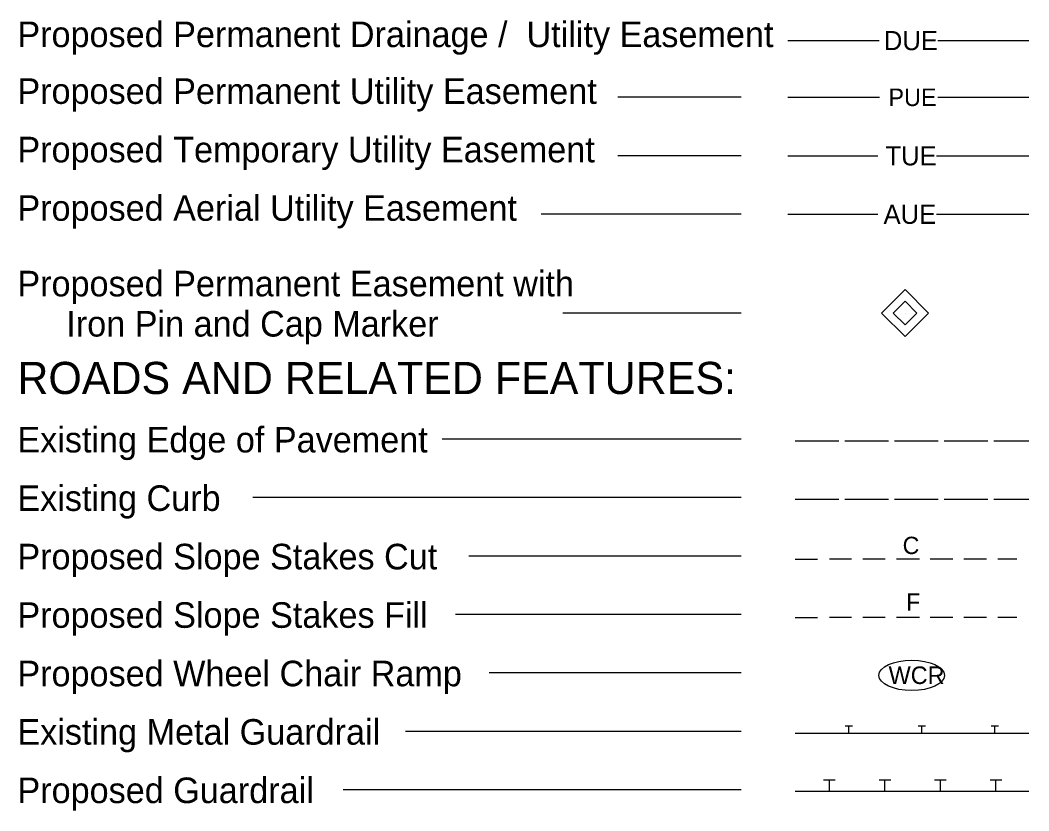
# Model space of a CAD drawing. Extents: x 573855 to 575539, y -53293 to -50956.
# Drawn here: x 574418.1 to 574763.4, y -53027.3 to -52756.7 of the extents above; entities that cross this region are included whole.
import ezdxf

# ---------------------------------------------------------------- set-up
doc = ezdxf.new("R2010")
doc.units = 0
for name, color, linetype in [('Prop Easement Permanent Drainage Utility', 7, 'Continuous'), ('Prop ROW Permanent Easement CELL', 7, 'Continuous'), ('Sheet Symbology CELL', 7, 'Continuous')]:
    doc.layers.add(name, color=color, linetype=linetype)

msp = doc.modelspace()

# ---------------------------------------------------------------- linework, layer by layer
at = {"layer": 'Prop Easement Permanent Drainage Utility'}
for p, q in [((574680.91, -52763.7), (574712.21, -52763.7)), ((574732.21, -52763.7), (574763.41, -52763.7))]:
    msp.add_line(p, q, dxfattribs=at)
at = {"layer": 'Prop ROW Permanent Easement CELL'}
msp.add_line((574721.05, -52856.95), (574721.05, -52856.95), dxfattribs=at)
for points in [[(574721.05, -52848.9), (574729.1, -52856.95), (574721.05, -52865), (574713, -52856.95)], [(574721.05, -52852.92), (574725.08, -52856.95), (574721.05, -52860.98), (574717.02, -52856.95)]]:
    msp.add_lwpolyline(points, close=True, dxfattribs=at)
at = {"layer": 'Sheet Symbology CELL'}
for p, q in [((574664.88, -52783.13), (574622.74, -52783.13)), ((574680.91, -52783.13), (574684.74, -52783.13)), ((574684.74, -52783.13), (574712.24, -52783.13)), ((574732.24, -52783.13), (574759.74, -52783.13)), ((574759.74, -52783.13), (574763.41, -52783.13)), ((574664.88, -52803.13), (574622.74, -52803.13)), ((574680.91, -52803.13), (574684.26, -52803.13)), ((574684.26, -52803.13), (574711.76, -52803.13)), ((574731.76, -52803.13), (574759.26, -52803.13)), ((574759.26, -52803.13), (574763.41, -52803.13)), ((574664.88, -52823.13), (574596.42, -52823.13)), ((574680.91, -52823.13), (574684.26, -52823.13)), ((574684.26, -52823.13), (574711.76, -52823.13)), ((574731.76, -52823.13), (574759.26, -52823.13)), ((574759.26, -52823.13), (574763.41, -52823.13)), ((574664.88, -52856.95), (574603.87, -52856.95)), ((574664.88, -52900.11), (574562.53, -52900.11)), ((574683.41, -52900.68), (574698.41, -52900.68)), ((574700.41, -52900.68), (574715.41, -52900.68)), ((574717.41, -52900.68), (574732.41, -52900.68)), ((574734.41, -52900.68), (574749.41, -52900.68)), ((574751.41, -52900.68), (574763.41, -52900.68)), ((574664.88, -52920.11), (574497.73, -52920.11)), ((574683.41, -52920.68), (574698.41, -52920.68)), ((574700.41, -52920.68), (574715.41, -52920.68)), ((574717.41, -52920.68), (574732.41, -52920.68)), ((574734.41, -52920.68), (574749.41, -52920.68)), ((574751.41, -52920.68), (574763.41, -52920.68)), ((574664.88, -52940.11), (574571.69, -52940.11)), ((574683.41, -52941.16), (574691.01, -52941.16)), ((574702.71, -52941.16), (574695.16, -52941.16)), ((574714.21, -52941.16), (574706.61, -52941.16)), ((574725.96, -52941.16), (574718.16, -52941.16)), ((574737.41, -52941.16), (574729.66, -52941.16)), ((574748.96, -52941.16), (574741.11, -52941.16)), ((574759.26, -52941.16), (574752.86, -52941.16)), ((574664.88, -52960.11), (574567.14, -52960.11)), ((574683.41, -52961.16), (574691.01, -52961.16)), ((574702.71, -52961.16), (574695.16, -52961.16)), ((574714.21, -52961.16), (574706.61, -52961.16)), ((574725.96, -52961.16), (574718.16, -52961.16)), ((574737.41, -52961.16), (574729.66, -52961.16)), ((574748.96, -52961.16), (574741.11, -52961.16)), ((574759.26, -52961.16), (574752.86, -52961.16)), ((574664.88, -52980.11), (574578.61, -52980.11)), ((574700.56, -52998.17), (574703.06, -52998.17)), ((574701.81, -53000.67), (574701.81, -52998.17)), ((574725.56, -52998.17), (574728.06, -52998.17)), ((574726.81, -53000.67), (574726.81, -52998.17)), ((574750.56, -52998.17), (574753.06, -52998.17)), ((574751.81, -53000.67), (574751.81, -52998.17)), ((574664.89, -53000.09), (574550.05, -53000.09)), ((574683.42, -53000.67), (574763.42, -53000.67)), ((574693.14, -53016.72), (574697.14, -53016.72)), ((574695.14, -53020.67), (574695.14, -53016.72)), ((574712.14, -53016.72), (574716.14, -53016.72)), ((574714.14, -53020.67), (574714.14, -53016.72)), ((574731.14, -53016.72), (574735.14, -53016.72)), ((574733.14, -53020.67), (574733.14, -53016.72)), ((574750.14, -53016.72), (574754.14, -53016.72)), ((574752.14, -53020.67), (574752.14, -53016.72)), ((574664.89, -53020.09), (574528.65, -53020.09)), ((574763.42, -53020.67), (574683.42, -53020.67))]:
    msp.add_line(p, q, dxfattribs=at)
msp.add_ellipse((574723.33, -52980.93), major_axis=(11.21, 0), ratio=0.462467, dxfattribs=at)

# ---------------------------------------------------------------- texts
at = {"layer": 'Prop Easement Permanent Drainage Utility'}
msp.add_text('DUE', height=6.55, dxfattribs=at).set_placement((574713.8, -52767))
at = {"layer": 'Sheet Symbology CELL'}
for s, height, p in [('Proposed Permanent Drainage /  Utility Easement', 8.75, (574417.13, -52765.96)), ('Proposed Permanent Utility Easement', 8.75, (574417.13, -52785.39)), ('PUE', 6, (574715.34, -52786.13)), ('Proposed Temporary Utility Easement', 8.75, (574417.13, -52805.39)), ('TUE', 6.55, (574714.34, -52806.43)), ('Proposed Aerial Utility Easement', 8.75, (574417.13, -52825.39)), ('AUE', 6.55, (574713.68, -52826.43)), ('Proposed Permanent Easement with', 8.75, (574417.13, -52851.25)), ('Iron Pin and Cap Marker', 8.75, (574433.89, -52865)), ('ROADS AND RELATED FEATURES:', 11, (574417.13, -52884.66)), ('Existing Edge of Pavement', 8.75, (574417.13, -52904.66)), ('Existing Curb', 8.75, (574417.13, -52924.66)), ('Proposed Slope Stakes Cut', 8.75, (574417.13, -52944.66)), ('C', 5.93, (574720.21, -52939.42)), ('F', 5.93, (574721.41, -52958.79)), ('Proposed Slope Stakes Fill', 8.75, (574417.13, -52964.66)), ('Proposed Wheel Chair Ramp', 8.75, (574417.13, -52984.66)), ('Existing Metal Guardrail', 8.75, (574417.14, -53004.64)), ('Proposed Guardrail', 8.75, (574417.15, -53024.63))]:
    msp.add_text(s, height=height, dxfattribs=at).set_placement(p)
msp.add_text('WCR', height=6, rotation=360, dxfattribs=at).set_placement((574715.41, -52983.88))

doc.saveas('drawing.dxf')
